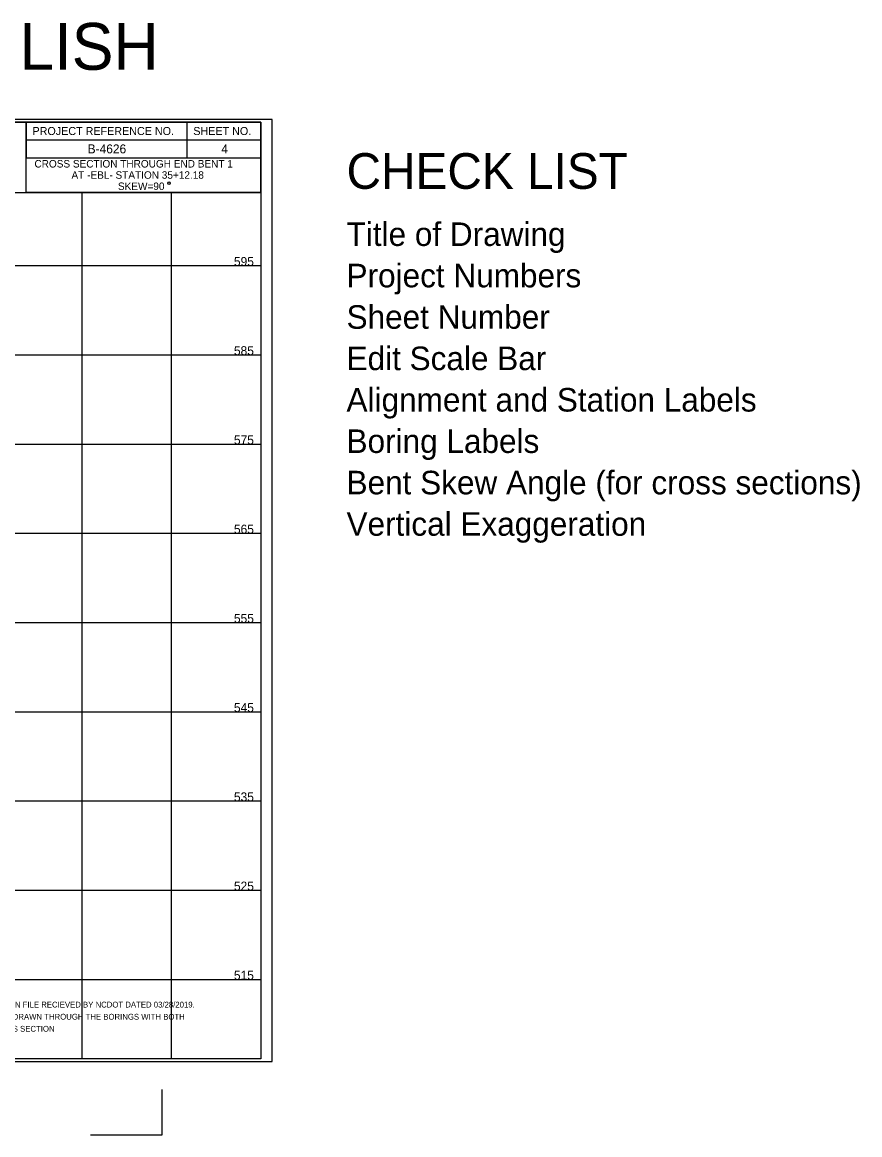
# Model space of a CAD drawing. Extents: x 278618 to 280654, y 171155 to 171855.
# Drawn here: x 280147.4 to 280241.2, y 171180.4 to 171305.1 of the extents above; entities that cross this region are included whole.
import ezdxf

# ---------------------------------------------------------------- set-up
doc = ezdxf.new("R2010")
doc.units = 0
for name, color, linetype in [('Exist Vertical Profile Ground Line', 7, 'Continuous'), ('Geotech Sheets and Borders Cell', 7, 'Continuous'), ('Prop Strc Sect_ Grid - minor', 7, 'Continuous'), ('Scratch_Level_0', 7, 'Continuous'), ('Scratch_Level_2', 7, 'Continuous'), ('Scratch_Level_4', 7, 'Continuous'), ('Sheet Plot Border Inside CELL', 7, 'Continuous')]:
    doc.layers.add(name, color=color, linetype=linetype)

msp = doc.modelspace()

# ---------------------------------------------------------------- linework, layer by layer
at = {"layer": 'Geotech Sheets and Borders Cell'}
for p, q in [((280165.84, 171293.86), (280165.84, 171289.86)), ((280147.83, 171291.86), (280174.12, 171291.86))]:
    msp.add_line(p, q, dxfattribs=at)
for points in [[(280024.12, 171293.86), (280174.12, 171293.86), (280174.12, 171188.86), (280024.12, 171188.86)], [(280121.53, 171285.96), (280174.12, 171285.96), (280174.12, 171293.86), (280121.53, 171293.86)], [(280147.83, 171289.86), (280174.12, 171289.86), (280174.12, 171293.86), (280147.83, 171293.86)], [(280147.83, 171293.86), (280174.12, 171293.86), (280174.12, 171285.96), (280147.83, 171285.96)]]:
    msp.add_lwpolyline(points, close=True, dxfattribs=at)
msp.add_circle((280163.82, 171287.02), 0.141, dxfattribs=at)
at = {"layer": 'Prop Strc Sect_ Grid - minor'}
for p, q in [((280154.12, 171188.86), (280154.12, 171285.96)), ((280164.12, 171188.86), (280164.12, 171285.96)), ((280174.12, 171277.74), (280024.12, 171277.74)), ((280174.12, 171267.74), (280024.12, 171267.74)), ((280174.12, 171257.74), (280024.12, 171257.74)), ((280174.12, 171247.74), (280024.12, 171247.74)), ((280174.12, 171237.74), (280024.12, 171237.74)), ((280174.12, 171227.74), (280024.12, 171227.74)), ((280174.12, 171217.74), (280024.12, 171217.74)), ((280174.12, 171207.74), (280024.12, 171207.74)), ((280174.12, 171197.74), (280024.12, 171197.74))]:
    msp.add_line(p, q, dxfattribs=at)
at = {"layer": 'Scratch_Level_0'}
msp.add_line((280175.37, 171294.14), (280175.37, 171294.14), dxfattribs=at)
at = {"layer": 'Scratch_Level_4'}
msp.add_lwpolyline([(280155.03, 171180.37), (280163.06, 171180.37), (280163.06, 171185.45)], dxfattribs=at)
at = {"layer": 'Sheet Plot Border Inside CELL'}
msp.add_lwpolyline([(280008.61, 171188.58), (280175.37, 171188.58), (280175.37, 171294.14), (280008.61, 171294.14)], close=True, dxfattribs=at)

# ---------------------------------------------------------------- texts
at = {"layer": 'Exist Vertical Profile Ground Line'}
for s, p in [('GROUNDLINE TAKEN FROM .TIN FILE RECIEVED BY NCDOT DATED 03/28/2019.', (280133.58, 171194.63)), ('INFERRED STRATIGRAPHY IS DRAWN THROUGH THE BORINGS WITH BOTH ', (280133.58, 171193.27)), ('PROJECTED ONTO THE CROSS SECTION', (280133.58, 171191.92))]:
    msp.add_text(s, height=0.65, dxfattribs=at).set_placement(p)
at = {"layer": 'Geotech Sheets and Borders Cell'}
for s, height, p in [('PROJECT REFERENCE NO.', 0.9, (280148.54, 171292.41)), ('SHEET NO.', 0.9, (280166.55, 171292.41)), ('B-4626', 1, (280154.72, 171290.36)), ('4', 1, (280169.69, 171290.36)), ('595', 1.001, (280171.1, 171277.74)), ('585', 1.001, (280171.1, 171267.74)), ('575', 1.001, (280171.1, 171257.74)), ('565', 1.001, (280171.1, 171247.74)), ('555', 1.001, (280171.1, 171237.74)), ('545', 1.001, (280171.1, 171227.74)), ('535', 1.001, (280171.1, 171217.74)), ('525', 1.001, (280171.1, 171207.74)), ('515', 1.001, (280171.1, 171197.74))]:
    msp.add_text(s, height=height, dxfattribs=at).set_placement(p)
for s, p in [('CROSS SECTION THROUGH END BENT 1    ', (280148.76, 171288.77)), ('AT -EBL- STATION 35+12.18 ', (280152.91, 171287.51)), ('SKEW=90', (280158.11, 171286.25))]:
    msp.add_text(s, height=0.84, rotation=360, dxfattribs=at).set_placement(p)
at = {"layer": 'Scratch_Level_2'}
msp.add_text('STRUCTURE PROFILE SHEET, ENGLISH', height=5.25, dxfattribs=at).set_placement((280027.32, 171299.72))
at = {"layer": 'Scratch_Level_4'}
for s, height, p in [('CHECK LIST', 4, (280183.71, 171286.38)), ('Title of Drawing', 2.64, (280183.71, 171279.98)), ('Project Numbers', 2.64, (280183.71, 171275.34)), ('Sheet Number', 2.64, (280183.71, 171270.7)), ('Edit Scale Bar', 2.64, (280183.71, 171266.06)), ('Alignment and Station Labels', 2.64, (280183.71, 171261.42)), ('Boring Labels', 2.64, (280183.71, 171256.78)), ('Bent Skew Angle (for cross sections)', 2.64, (280183.71, 171252.14)), ('Vertical Exaggeration', 2.64, (280183.71, 171247.5))]:
    msp.add_text(s, height=height, dxfattribs=at).set_placement(p)

doc.saveas('drawing.dxf')
